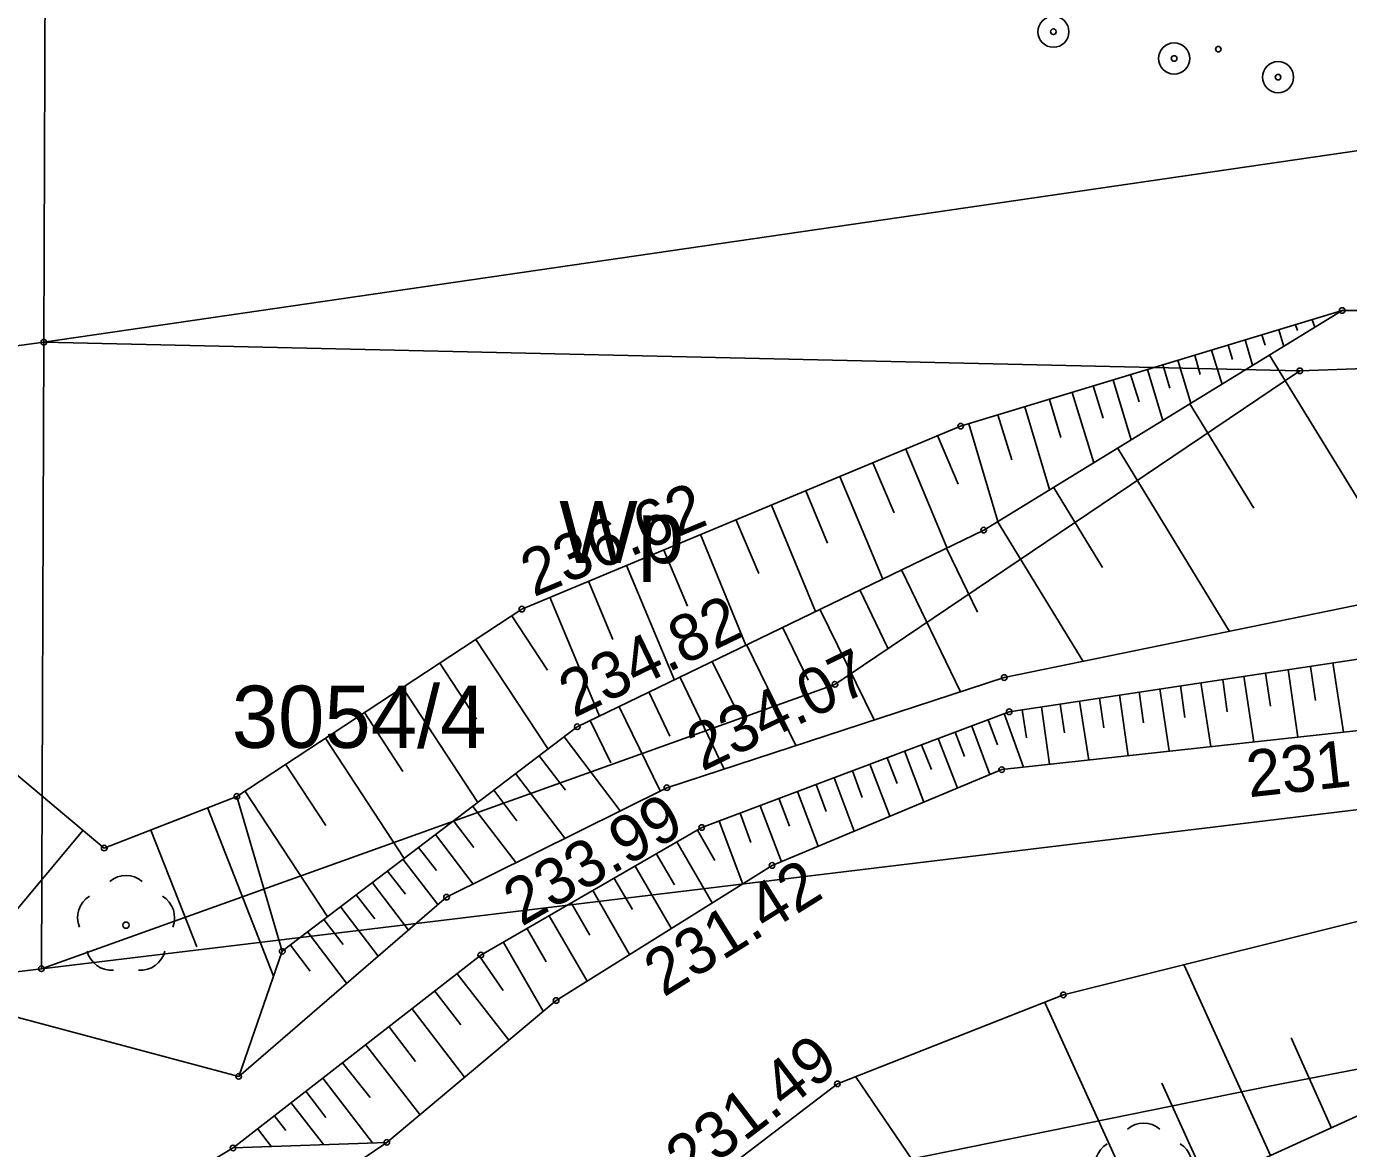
# Model space of a CAD drawing. Extents: x 6596400 to 6597200, y 5539751 to 5540251.
# Drawn here: x 6596752.84 to 6596774.08, y 5540061.24 to 5540079.28 of the extents above; entities that cross this region are included whole.
import ezdxf

# ---------------------------------------------------------------- set-up
doc = ezdxf.new("R2010")
doc.units = 0
for name, color, linetype in [('000 Inne (niezydentyfikowane)', 7, 'Continuous'), ('140-Punkty robocze', 7, 'Continuous'), ('203-punkt graniczny', 7, 'Continuous'), ('210-oznaczenie konturu użytku gruntowego', 7, 'Continuous'), ('211-numer działki ewidencyjnej', 7, 'Continuous'), ('218-kontur użytku gruntowego', 7, 'Continuous'), ('219-działka ewidencyjna', 7, 'Continuous'), ('drzewo liściaste', 7, 'Continuous'), ('Linia obszaru zagospodarowania terenu', 7, 'Continuous'), ('pikieta sztuczna', 7, 'Continuous'), ('pikieta sztuczna-Atr2', 7, 'Continuous'), ('rów melioracyjny (poligon)', 7, 'Continuous'), ('skarpa nieumocniona', 7, 'Continuous'), ('skarpa umocniona', 7, 'Continuous'), ('właz do komory lub kanału - okrągły', 7, 'Continuous')]:
    doc.layers.add(name, color=color, linetype=linetype)

# ---------------------------------------------------------------- blocks, each defined once
blk = doc.blocks.new('203')
blk.add_circle((0, 0), 0.045)
blk = doc.blocks.new('OP021')
blk.add_circle((0, 0), 0.05)
for centre, start, end in [((0, 0.4), 49.272, 130.728), ((-0.38, 0.124), 121.308, 202.548), ((0.38, 0.124), 337.452, 58.692), ((-0.235, -0.324), 193.221, 274.871), ((0.235, -0.324), 265.129, 346.779)]:
    blk.add_arc(centre, 0.4, start, end)
blk = doc.blocks.new('US22')
blk.add_circle((0, 0), 0.25)
blk = doc.blocks.new('PIKIETA')
blk.add_circle((0, 0), 0.045)
blk = doc.blocks.new('PW01')
blk.add_circle((0, 0), 0.045)

msp = doc.modelspace()

# ---------------------------------------------------------------- linework, layer by layer
at = {"layer": '000 Inne (niezydentyfikowane)'}
for p, q in [((6596772.81, 5540073.99), (6596775.16, 5540070.17)), ((6596771.53, 5540073.21), (6596772.56, 5540071.53)), ((6596770.37, 5540072.5), (6596772.17, 5540069.55)), ((6596769.34, 5540071.87), (6596770.13, 5540070.58)), ((6596768.44, 5540071.32), (6596769.82, 5540069.07)), ((6596767.62, 5540070.89), (6596768.12, 5540069.86)), ((6596766.9, 5540070.54), (6596767.85, 5540068.58)), ((6596766.23, 5540070.22), (6596766.68, 5540069.28)), ((6596765.59, 5540069.91), (6596766.46, 5540068.13)), ((6596764.99, 5540069.62), (6596765.4, 5540068.77)), ((6596764.41, 5540069.34), (6596765.2, 5540067.72)), ((6596763.86, 5540069.07), (6596764.24, 5540068.3)), ((6596772.75, 5540068.88), (6596772.83, 5540068.35)), ((6596773.11, 5540068.94), (6596773.27, 5540067.85)), ((6596773.47, 5540068.99), (6596773.55, 5540068.44)), ((6596773.83, 5540069.05), (6596774, 5540067.93)), ((6596763.34, 5540068.82), (6596764.05, 5540067.34)), ((6596771.38, 5540068.68), (6596771.45, 5540068.17)), ((6596771.71, 5540068.73), (6596771.87, 5540067.7)), ((6596772.06, 5540068.78), (6596772.13, 5540068.26)), ((6596772.4, 5540068.83), (6596772.56, 5540067.77)), ((6596762.84, 5540068.58), (6596763.18, 5540067.87)), ((6596769.76, 5540068.43), (6596769.91, 5540067.48)), ((6596770.08, 5540068.48), (6596770.15, 5540068)), ((6596770.4, 5540068.53), (6596770.54, 5540067.55)), ((6596770.72, 5540068.58), (6596770.79, 5540068.08)), ((6596771.05, 5540068.63), (6596771.2, 5540067.63)), ((6596762.36, 5540068.35), (6596763.02, 5540066.99)), ((6596768.55, 5540068.23), (6596768.86, 5540067.37)), ((6596768.84, 5540068.29), (6596768.91, 5540067.84)), ((6596769.15, 5540068.34), (6596769.28, 5540067.42)), ((6596769.45, 5540068.38), (6596769.52, 5540067.92)), ((6596761.9, 5540068.12), (6596762.23, 5540067.44)), ((6596768.03, 5540068.03), (6596768.32, 5540067.25)), ((6596768.29, 5540068.13), (6596768.44, 5540067.73)), ((6596761.48, 5540067.86), (6596762.38, 5540066.67)), ((6596767.49, 5540067.83), (6596767.8, 5540067.03)), ((6596767.76, 5540067.93), (6596767.91, 5540067.54)), ((6596766.95, 5540067.63), (6596767.26, 5540066.81)), ((6596767.22, 5540067.73), (6596767.38, 5540067.33)), ((6596761.08, 5540067.55), (6596761.5, 5540067)), ((6596766.39, 5540067.42), (6596766.71, 5540066.58)), ((6596766.67, 5540067.52), (6596766.83, 5540067.11)), ((6596760.7, 5540067.27), (6596761.49, 5540066.23)), ((6596765.82, 5540067.2), (6596766.14, 5540066.34)), ((6596766.11, 5540067.31), (6596766.27, 5540066.88)), ((6596760.35, 5540067), (6596760.72, 5540066.51)), ((6596765.23, 5540066.98), (6596765.56, 5540066.1)), ((6596765.53, 5540067.09), (6596765.69, 5540066.66)), ((6596760.01, 5540066.74), (6596760.71, 5540065.83)), ((6596764.63, 5540066.75), (6596764.97, 5540065.85)), ((6596764.93, 5540066.87), (6596765.1, 5540066.42)), ((6596764.31, 5540066.63), (6596764.48, 5540066.16)), ((6596759.7, 5540066.51), (6596760.03, 5540066.08)), ((6596763.62, 5540066.36), (6596763.9, 5540065.87)), ((6596763.97, 5540066.5), (6596764.35, 5540065.49)), ((6596759.41, 5540066.29), (6596760.02, 5540065.49)), ((6596763.29, 5540066.17), (6596763.86, 5540065.19)), ((6596758.89, 5540065.89), (6596759.45, 5540065.16)), ((6596759.14, 5540066.08), (6596759.43, 5540065.71)), ((6596762.96, 5540065.98), (6596763.25, 5540065.48)), ((6596758.64, 5540065.7), (6596758.93, 5540065.33)), ((6596762.62, 5540065.78), (6596763.2, 5540064.78)), ((6596758.4, 5540065.51), (6596758.98, 5540064.75)), ((6596762.28, 5540065.59), (6596762.58, 5540065.08)), ((6596758.14, 5540065.32), (6596758.44, 5540064.93)), ((6596761.94, 5540065.39), (6596762.53, 5540064.36)), ((6596757.89, 5540065.12), (6596758.49, 5540064.33)), ((6596761.59, 5540065.19), (6596761.89, 5540064.67)), ((6596757.62, 5540064.92), (6596757.93, 5540064.52)), ((6596761.24, 5540064.98), (6596761.85, 5540063.93)), ((6596757.36, 5540064.72), (6596757.98, 5540063.9)), ((6596760.88, 5540064.78), (6596761.19, 5540064.24)), ((6596757.08, 5540064.51), (6596757.4, 5540064.09)), ((6596760.5, 5540064.56), (6596761.14, 5540063.45)), ((6596760.12, 5540064.33), (6596760.5, 5540063.78)), ((6596772.83, 5540061.13), (6596771.44, 5540064.19)), ((6596759.76, 5540064.05), (6596760.59, 5540062.98)), ((6596759.4, 5540063.77), (6596759.82, 5540063.23)), ((6596770.75, 5540060.18), (6596769.2, 5540063.59)), ((6596759.03, 5540063.49), (6596759.88, 5540062.39)), ((6596758.66, 5540063.2), (6596759.09, 5540062.64)), ((6596758.29, 5540062.91), (6596759.16, 5540061.79)), ((6596773.81, 5540061.57), (6596773.16, 5540063.02)), ((6596757.92, 5540062.62), (6596758.36, 5540062.06)), ((6596757.6, 5540062.37), (6596758.4, 5540061.33)), ((6596768.62, 5540058.79), (6596766.16, 5540062.4)), ((6596771.82, 5540060.67), (6596771.08, 5540062.29)), ((6596757.33, 5540062.16), (6596757.65, 5540061.74)), ((6596757.09, 5540061.98), (6596757.62, 5540061.3)), ((6596756.82, 5540061.77), (6596757.01, 5540061.53)), ((6596756.55, 5540061.56), (6596756.78, 5540061.27))]:
    msp.add_line(p, q, dxfattribs=at)
for points in [[(6596772.96, 5540074.4), (6596773.04, 5540074.13)], [(6596773.23, 5540074.48), (6596773.26, 5540074.39)], [(6596773.5, 5540074.56), (6596773.54, 5540074.44)], [(6596772.42, 5540074.24), (6596772.54, 5540073.83)], [(6596772.69, 5540074.32), (6596772.74, 5540074.15)], [(6596771.61, 5540073.99), (6596771.7, 5540073.68)], [(6596771.88, 5540074.07), (6596772.05, 5540073.52)], [(6596772.15, 5540074.15), (6596772.22, 5540073.92)], [(6596770.85, 5540073.76), (6596771.1, 5540072.94)], [(6596771.1, 5540073.84), (6596771.21, 5540073.46)], [(6596771.34, 5540073.91), (6596771.55, 5540073.22)], [(6596770.3, 5540073.59), (6596770.59, 5540072.63)], [(6596770.58, 5540073.68), (6596770.72, 5540073.24)], [(6596769.64, 5540073.39), (6596769.99, 5540072.26)], [(6596769.98, 5540073.5), (6596770.14, 5540072.98)], [(6596768.88, 5540073.16), (6596769.28, 5540071.83)], [(6596769.28, 5540073.28), (6596769.46, 5540072.67)], [(6596768.45, 5540073.03), (6596768.67, 5540072.31)], [(6596767.48, 5540072.7), (6596767.81, 5540071.92)], [(6596767.98, 5540072.89), (6596768.45, 5540071.32)], [(6596766.97, 5540072.48), (6596767.63, 5540070.9)], [(6596766.44, 5540072.26), (6596766.78, 5540071.46)], [(6596765.91, 5540072.04), (6596766.6, 5540070.39)], [(6596765.36, 5540071.81), (6596765.71, 5540070.97)], [(6596764.81, 5540071.58), (6596765.52, 5540069.87)], [(6596764.24, 5540071.35), (6596764.61, 5540070.48)], [(6596763.67, 5540071.11), (6596764.4, 5540069.33)], [(6596763.08, 5540070.86), (6596763.46, 5540069.96)], [(6596762.48, 5540070.61), (6596763.25, 5540068.77)], [(6596761.87, 5540070.36), (6596762.26, 5540069.42)], [(6596761.25, 5540070.1), (6596762.05, 5540068.19)], [(6596760.64, 5540069.8), (6596761.21, 5540068.93)], [(6596760.06, 5540069.42), (6596761.22, 5540067.66)], [(6596759.48, 5540069.04), (6596760.07, 5540068.14)], [(6596758.88, 5540068.65), (6596760.09, 5540066.8)], [(6596758.27, 5540068.25), (6596758.89, 5540067.3)], [(6596757.64, 5540067.84), (6596758.91, 5540065.9)], [(6596757, 5540067.42), (6596757.65, 5540066.43)], [(6596756.35, 5540066.99), (6596757.68, 5540064.96)], [(6596755.75, 5540066.72), (6596756.81, 5540064.01)], [(6596753.75, 5540066.36), (6596751.5, 5540063.67)], [(6596754.84, 5540066.36), (6596755.58, 5540064.48)]]:
    msp.add_lwpolyline(points, dxfattribs=at)
at = {"layer": '218-kontur użytku gruntowego'}
for points in [[(6596753.12, 5540074.2), (6596753.14, 5540080.12)], [(6596753.14, 5540080.12), (6596753.12, 5540074.2)], [(6596753.12, 5540074.2), (6596783.29, 5540078.6)], [(6596783.29, 5540078.6), (6596753.12, 5540074.2)], [(6596745.91, 5540073.23), (6596753.12, 5540074.2)], [(6596753.12, 5540074.2), (6596745.91, 5540073.23)], [(6596753.08, 5540064.13), (6596753.12, 5540074.2)], [(6596753.12, 5540074.2), (6596753.08, 5540064.13)], [(6596773.3, 5540073.74), (6596753.12, 5540074.2)], [(6596753.12, 5540074.2), (6596773.3, 5540073.74)], [(6596785.82, 5540074.19), (6596773.3, 5540073.74)], [(6596773.3, 5540073.74), (6596785.82, 5540074.19)], [(6596773.3, 5540073.74), (6596765.83, 5540068.7)], [(6596765.83, 5540068.7), (6596773.3, 5540073.74)], [(6596765.83, 5540068.7), (6596753.08, 5540064.13)], [(6596753.08, 5540064.13), (6596765.83, 5540068.7)], [(6596753.08, 5540064.13), (6596786.16, 5540068.13)], [(6596786.16, 5540068.13), (6596753.08, 5540064.13)], [(6596753.08, 5540064.13), (6596745.74, 5540063.25)], [(6596745.74, 5540063.25), (6596753.08, 5540064.13)]]:
    msp.add_lwpolyline(points, dxfattribs=at)
at = {"layer": '219-działka ewidencyjna'}
for points in [[(6596753.12, 5540074.2), (6596753.14, 5540080.12)], [(6596753.12, 5540074.2), (6596783.29, 5540078.6)], [(6596745.91, 5540073.23), (6596753.12, 5540074.2)], [(6596753.08, 5540064.13), (6596753.12, 5540074.2)], [(6596753.12, 5540074.2), (6596773.3, 5540073.74)], [(6596773.3, 5540073.74), (6596785.82, 5540074.19)], [(6596765.83, 5540068.7), (6596773.3, 5540073.74)], [(6596753.08, 5540064.13), (6596765.83, 5540068.7)], [(6596753.08, 5540064.13), (6596786.16, 5540068.13)], [(6596745.74, 5540063.25), (6596753.08, 5540064.13)]]:
    msp.add_lwpolyline(points, dxfattribs=at)
at = {"layer": 'Linia obszaru zagospodarowania terenu'}
msp.add_lwpolyline([(6596720.263, 5540058.387), (6596728.96, 5540057.84), (6596731.45, 5540057.76), (6596731.02, 5540064.64), (6596745.49, 5540064.58), (6596746.99, 5540056.99), (6596772.84, 5540062.25), (6596786.21, 5540064.83), (6596807.99, 5540057.58), (6596818.837, 5540049.192)], dxfattribs=at)
at = {"layer": 'rów melioracyjny (poligon)'}
for points in [[(6596820.208, 5540051.05), (6596817.24, 5540053.08), (6596812.31, 5540056.77), (6596808.36, 5540059.4), (6596802.55, 5540062.58), (6596795.13, 5540065.25), (6596788.99, 5540067.23), (6596782.3, 5540068.04), (6596775.52, 5540068.1), (6596768.51, 5540067.33), (6596764.82, 5540065.79), (6596761.35, 5540063.62), (6596758.63, 5540061.34), (6596754.58, 5540058.6), (6596752.07, 5540056.28), (6596746.75, 5540055.19), (6596741.65, 5540054.82), (6596742.01, 5540050.53), (6596747.46, 5540050.98), (6596751.88, 5540051.19), (6596756.01, 5540053.96), (6596757.53, 5540054.97), (6596761.73, 5540059.12)], [(6596761.73, 5540059.12), (6596765.87, 5540062.28), (6596769.5, 5540063.71), (6596775.27, 5540065.15), (6596782.49, 5540064.38), (6596788.18, 5540063.76), (6596793.92, 5540062.6), (6596807.97, 5540055.99), (6596815, 5540051.7), (6596818.611, 5540048.887)]]:
    msp.add_lwpolyline(points, dxfattribs=at)
at = {"layer": 'skarpa nieumocniona'}
for points in [[(6596756.22, 5540066.9), (6596754.09, 5540066.07), (6596752.07, 5540067.76), (6596750.47, 5540074), (6596751.32, 5540077.29), (6596748.52, 5540081.03), (6596740.72, 5540079.85), (6596740.68, 5540078.45), (6596742.94, 5540074), (6596746.51, 5540071.34), (6596747.03, 5540064.86), (6596756.25, 5540062.4), (6596756.95, 5540064.41)], [(6596756.22, 5540066.9), (6596754.09, 5540066.07), (6596752.07, 5540067.76), (6596750.47, 5540074), (6596751.32, 5540077.29), (6596748.52, 5540081.03), (6596740.72, 5540079.85), (6596740.68, 5540078.45), (6596742.94, 5540074), (6596746.51, 5540071.34), (6596747.03, 5540064.86), (6596756.25, 5540062.4), (6596756.95, 5540064.41)], [(6596756.16, 5540061.25), (6596751.77, 5540058.62), (6596746.79, 5540058.12), (6596745.06, 5540060.97), (6596743.75, 5540062.98), (6596744.34, 5540066.61), (6596742.94, 5540074), (6596740.68, 5540078.45), (6596741.68, 5540074.92), (6596743.25, 5540066.3), (6596742.47, 5540061.97), (6596741.65, 5540054.82), (6596746.75, 5540055.19), (6596752.07, 5540056.28), (6596754.58, 5540058.6), (6596758.63, 5540061.34)], [(6596756.16, 5540061.25), (6596751.77, 5540058.62), (6596746.79, 5540058.12), (6596745.06, 5540060.97), (6596743.75, 5540062.98), (6596744.34, 5540066.61), (6596742.94, 5540074), (6596740.68, 5540078.45), (6596741.68, 5540074.92), (6596743.25, 5540066.3), (6596742.47, 5540061.97), (6596741.65, 5540054.82), (6596746.75, 5540055.19), (6596752.07, 5540056.28), (6596754.58, 5540058.6), (6596758.63, 5540061.34)], [(6596773.98, 5540074.71), (6596767.85, 5540072.85), (6596760.8, 5540069.91), (6596756.22, 5540066.9), (6596756.95, 5540064.41), (6596761.69, 5540068.02), (6596768.22, 5540071.18)], [(6596773.98, 5540074.71), (6596767.85, 5540072.85), (6596760.8, 5540069.91), (6596756.22, 5540066.9), (6596756.95, 5540064.41), (6596761.69, 5540068.02), (6596768.22, 5540071.18)]]:
    msp.add_lwpolyline(points, close=True, dxfattribs=at)
at = {"layer": 'skarpa umocniona'}
msp.add_lwpolyline([(6596788.93, 5540069.36), (6596781.56, 5540070.33), (6596775.65, 5540070.27), (6596768.55, 5540068.81), (6596763.13, 5540067.04), (6596759.59, 5540065.28), (6596756.25, 5540062.4), (6596756.95, 5540064.41), (6596761.69, 5540068.02), (6596768.22, 5540071.18), (6596773.98, 5540074.71), (6596780.46, 5540074.71), (6596784.99, 5540074.54), (6596793.19, 5540073.11)], dxfattribs=at)
msp.add_lwpolyline([(6596788.93, 5540069.36), (6596781.56, 5540070.33), (6596775.65, 5540070.27), (6596768.55, 5540068.81), (6596763.13, 5540067.04), (6596759.59, 5540065.28), (6596756.25, 5540062.4), (6596756.95, 5540064.41), (6596761.69, 5540068.02), (6596768.22, 5540071.18), (6596773.98, 5540074.71), (6596780.46, 5540074.71), (6596784.99, 5540074.54), (6596793.19, 5540073.11)], dxfattribs=at)
for points in [[(6596781.29, 5540069.35), (6596788.9, 5540068.52), (6596795.46, 5540066.97), (6596804.46, 5540064.28), (6596817.35, 5540056.24), (6596821.61, 5540052.95), (6596820.21, 5540051.05), (6596817.24, 5540053.08), (6596812.31, 5540056.77), (6596808.36, 5540059.4), (6596802.55, 5540062.58), (6596795.13, 5540065.25), (6596788.99, 5540067.23), (6596782.3, 5540068.04), (6596775.52, 5540068.1), (6596768.51, 5540067.33), (6596764.82, 5540065.79), (6596761.35, 5540063.62), (6596758.63, 5540061.34), (6596756.16, 5540061.25), (6596760.14, 5540064.35), (6596763.69, 5540066.4), (6596768.63, 5540068.26), (6596775.9, 5540069.36)], [(6596781.29, 5540069.35), (6596788.9, 5540068.52), (6596795.46, 5540066.97), (6596804.46, 5540064.28), (6596817.35, 5540056.24), (6596821.61, 5540052.95), (6596820.21, 5540051.05), (6596817.24, 5540053.08), (6596812.31, 5540056.77), (6596808.36, 5540059.4), (6596802.55, 5540062.58), (6596795.13, 5540065.25), (6596788.99, 5540067.23), (6596782.3, 5540068.04), (6596775.52, 5540068.1), (6596768.51, 5540067.33), (6596764.82, 5540065.79), (6596761.35, 5540063.62), (6596758.63, 5540061.34), (6596756.16, 5540061.25), (6596760.14, 5540064.35), (6596763.69, 5540066.4), (6596768.63, 5540068.26), (6596775.9, 5540069.36)], [(6596782.49, 5540064.38), (6596788.18, 5540063.76), (6596793.92, 5540062.6), (6596807.97, 5540055.99), (6596815, 5540051.7), (6596818.61, 5540048.89), (6596817.09, 5540046.82), (6596813.04, 5540049.86), (6596807.32, 5540053.71), (6596801, 5540055.88), (6596793.16, 5540059.3), (6596788.6, 5540060.8), (6596783.73, 5540060.81), (6596779.28, 5540061), (6596774.44, 5540061.86), (6596770.5, 5540060.07), (6596764.63, 5540056.07), (6596761.73, 5540059.12), (6596765.87, 5540062.28), (6596769.5, 5540063.71), (6596775.27, 5540065.15)], [(6596782.49, 5540064.38), (6596788.18, 5540063.76), (6596793.92, 5540062.6), (6596807.97, 5540055.99), (6596815, 5540051.7), (6596818.61, 5540048.89), (6596817.09, 5540046.82), (6596813.04, 5540049.86), (6596807.32, 5540053.71), (6596801, 5540055.88), (6596793.16, 5540059.3), (6596788.6, 5540060.8), (6596783.73, 5540060.81), (6596779.28, 5540061), (6596774.44, 5540061.86), (6596770.5, 5540060.07), (6596764.63, 5540056.07), (6596761.73, 5540059.12), (6596765.87, 5540062.28), (6596769.5, 5540063.71), (6596775.27, 5540065.15)]]:
    msp.add_lwpolyline(points, close=True, dxfattribs=at)

# ---------------------------------------------------------------- block references
at = {"layer": '140-Punkty robocze'}
for p in [(6596769.34, 5540079.19), (6596771.99, 5540078.91), (6596771.28, 5540078.76), (6596772.95, 5540078.46), (6596767.85, 5540072.85), (6596768.22, 5540071.18), (6596760.8, 5540069.91), (6596768.55, 5540068.81), (6596768.63, 5540068.26), (6596761.69, 5540068.02), (6596768.51, 5540067.33), (6596756.22, 5540066.9), (6596763.13, 5540067.04), (6596763.69, 5540066.4), (6596754.09, 5540066.07), (6596764.82, 5540065.79), (6596759.59, 5540065.28), (6596756.95, 5540064.41), (6596760.14, 5540064.35), (6596761.35, 5540063.62), (6596769.5, 5540063.71), (6596756.25, 5540062.4), (6596765.87, 5540062.28), (6596756.16, 5540061.25), (6596758.63, 5540061.34)]:
    msp.add_blockref('PIKIETA', p, dxfattribs=at)
at = {"layer": '203-punkt graniczny'}
for p in [(6596753.12, 5540074.2), (6596773.3, 5540073.74), (6596765.83, 5540068.7), (6596753.08, 5540064.13)]:
    msp.add_blockref('203', p, dxfattribs=at)
at = {"layer": 'drzewo liściaste'}
for p in [(6596754.44, 5540064.83), (6596770.79, 5540060.85)]:
    msp.add_blockref('OP021', p, dxfattribs=at)
at = {"layer": 'pikieta sztuczna'}
for p in [(6596773.98, 5540074.71), (6596760.8, 5540069.91), (6596761.69, 5540068.02), (6596763.13, 5540067.04), (6596763.69, 5540066.4), (6596764.82, 5540065.79), (6596765.87, 5540062.28)]:
    msp.add_blockref('PW01', p, dxfattribs=at)
at = {"layer": 'właz do komory lub kanału - okrągły'}
for p in [(6596769.34, 5540079.19), (6596771.28, 5540078.76), (6596772.95, 5540078.46)]:
    msp.add_blockref('US22', p, dxfattribs=at)

# ---------------------------------------------------------------- texts
at = {"layer": '210-oznaczenie konturu użytku gruntowego'}
msp.add_text('Wp', height=1, dxfattribs=at).set_placement((6596761.4, 5540070.65))
at = {"layer": '211-numer działki ewidencyjnej'}
msp.add_text('3054/4', height=1, dxfattribs=at).set_placement((6596756.14, 5540067.68))
at = {"layer": 'pikieta sztuczna-Atr2'}
for s, rotation, p in [('236.62', 22.637, (6596760.989, 5540070.098)), ('234.82', 25.823, (6596761.637, 5540068.155)), ('234.07', 25.823, (6596763.697, 5540067.295)), ('231.40', 6.268, (6596772.482, 5540066.884)), ('233.99', 30.005, (6596760.795, 5540064.801)), ('231.42', 32.02, (6596763.078, 5540063.664)), ('231.49', 37.354, (6596763.485, 5540060.664))]:
    msp.add_text(s, height=0.75, rotation=rotation, dxfattribs=at).set_placement(p)

doc.saveas('drawing.dxf')
